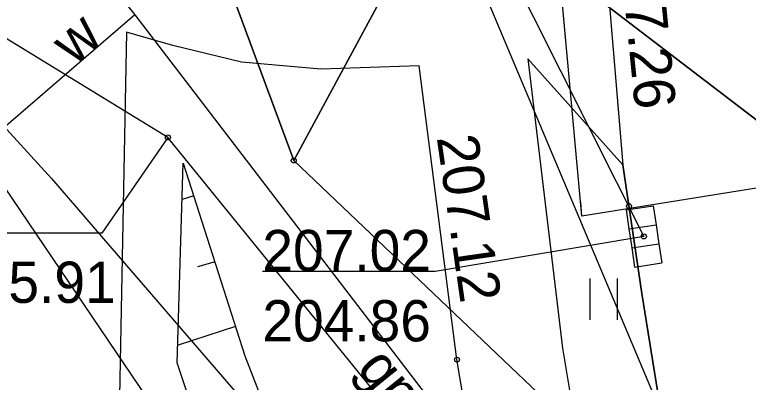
# Model space of a CAD drawing. Extents: x 6512400 to 6513200, y 6022500 to 6022750.
# Drawn here: x 6512830.73 to 6512844.08, y 6022647.71 to 6022654.39 of the extents above; entities that cross this region are included whole.
import ezdxf

# ---------------------------------------------------------------- set-up
doc = ezdxf.new("R2010")
doc.units = 0
for name, color, linetype in [('203-punkt graniczny', 7, 'Continuous'), ('218-kontur użytku gruntowego', 7, 'Continuous'), ('219-działka ewidencyjna', 7, 'Continuous'), ('820-Skarpa nieumocniona', 7, 'Continuous'), ('823-Szczyt skarpy nieumocninej', 7, 'Continuous'), ('824-Podnóże skarpy nieumocninej', 7, 'Continuous'), ('940-Trawnik symb. poj.', 7, 'Continuous'), ('chodnik (powierzchnia)', 7, 'Continuous'), ('inna obudowa przewodu - sieć elektroenergetyczna (linia)', 7, 'Continuous'), ('jezdnia (powierzchnia)', 7, 'Continuous'), ('kratka ściekowa (punkt)', 7, 'Continuous'), ('krawężnik (linia)', 7, 'Continuous'), ('przewód elektroenergetyczny (linia)', 7, 'Continuous'), ('przewód gazowy (linia)', 7, 'Continuous'), ('przewód gazowy (linia)-Atr1', 7, 'Continuous'), ('przewód kanalizacyjny (linia)', 7, 'Continuous'), ('przewód wodociągowy (linia)', 7, 'Continuous'), ('przewód wodociągowy (linia)-Atr1', 7, 'Continuous'), ('punkt o określonej wysokości (sieć gazowa)', 7, 'Continuous'), ('punkt o określonej wysokości (sieć gazowa)-Atr2', 7, 'Continuous'), ('punkt o określonej wysokości (sieć gazowa)-Atr3', 7, 'Continuous'), ('punkt o określonej wysokości (sieć kanalizacyjna)', 7, 'Continuous'), ('punkt o określonej wysokości (sieć kanalizacyjna)-Atr2', 7, 'Continuous'), ('punkt o określonej wysokości (sieć kanalizacyjna)-Atr3', 7, 'Continuous'), ('punkt wysokościowy sztuczny', 7, 'Continuous'), ('punkt wysokościowy sztuczny-Atr2', 7, 'Continuous')]:
    doc.layers.add(name, color=color, linetype=linetype)

# ---------------------------------------------------------------- blocks, each defined once
blk = doc.blocks.new('203')
blk.add_circle((0, 0), 0.045)
blk = doc.blocks.new('PW02')
blk.add_circle((0, 0), 0.045)
blk = doc.blocks.new('940P')
for p, q in [((-0.25, -0.375), (-0.25, 0.375)), ((0.25, -0.375), (0.25, 0.375))]:
    blk.add_line(p, q)
blk = doc.blocks.new('PW01')
blk.add_circle((0, 0), 0.045)
blk = doc.blocks.new('US05')
for p, q in [((-0.525, -0.25), (-0.525, 0.25)), ((-0.525, 0.25), (-0.175, 0.25)), ((-0.175, -0.25), (-0.175, 0.25)), ((-0.175, 0.25), (0.175, 0.25)), ((0.175, -0.25), (0.175, 0.25)), ((0.175, 0.25), (0.525, 0.25)), ((0.525, -0.25), (0.525, 0.25)), ((-0.525, -0.25), (-0.175, -0.25)), ((-0.175, -0.25), (0.175, -0.25)), ((0.175, -0.25), (0.525, -0.25))]:
    blk.add_line(p, q)

msp = doc.modelspace()

# ---------------------------------------------------------------- linework, layer by layer
at = {"layer": '218-kontur użytku gruntowego'}
for points in [[(6512828.67, 6022670.98), (6512835.81, 6022651.74)], [(6512835.81, 6022651.74), (6512828.67, 6022670.98)], [(6512835.81, 6022651.74), (6512838.55, 6022656.82)], [(6512838.55, 6022656.82), (6512835.81, 6022651.74)], [(6512838.55, 6022656.82), (6512856.49, 6022643.11)], [(6512856.49, 6022643.11), (6512838.55, 6022656.82)], [(6512835.81, 6022651.74), (6512852.34, 6022636.01)], [(6512852.34, 6022636.01), (6512835.81, 6022651.74)]]:
    msp.add_lwpolyline(points, dxfattribs=at)
at = {"layer": '219-działka ewidencyjna'}
for points in [[(6512828.67, 6022670.98), (6512835.81, 6022651.74)], [(6512838.55, 6022656.82), (6512835.81, 6022651.74)], [(6512856.49, 6022643.11), (6512838.55, 6022656.82)], [(6512852.34, 6022636.01), (6512835.81, 6022651.74)]]:
    msp.add_lwpolyline(points, dxfattribs=at)
at = {"layer": '820-Skarpa nieumocniona'}
for p, q in [((6512833.99, 6022651.1), (6512833.78, 6022651.03)), ((6512834.38, 6022649.9), (6512834.06, 6022649.81)), ((6512834.75, 6022648.72), (6512833.71, 6022648.38))]:
    msp.add_line(p, q, dxfattribs=at)
at = {"layer": '823-Szczyt skarpy nieumocninej'}
msp.add_lwpolyline([(6512833.8, 6022651.69), (6512834.92, 6022648.19), (6512835.69, 6022646.2), (6512839.8, 6022638.81), (6512840.88, 6022636.68), (6512842.42, 6022630.86), (6512843.78, 6022626.35)], dxfattribs=at)
at = {"layer": '824-Podnóże skarpy nieumocninej'}
msp.add_lwpolyline([(6512843.78, 6022626.35), (6512842.81, 6022626.09), (6512839.81, 6022635.37), (6512839.21, 6022636.76), (6512838.73, 6022638.25), (6512834.42, 6022645.85), (6512833.69, 6022648.06), (6512833.8, 6022651.69)], dxfattribs=at)
at = {"layer": 'chodnik (powierzchnia)'}
for points in [[(6512832.77, 6022654.07), (6512832.63, 6022646.82), (6512837.95, 6022638.9), (6512839.21, 6022636.76), (6512839.81, 6022635.37), (6512842.81, 6022626.09), (6512843.78, 6022626.35), (6512842.42, 6022630.86), (6512840.88, 6022636.68), (6512839.84, 6022641.88), (6512838.78, 6022648.12), (6512838.09, 6022653.46), (6512836.3, 6022653.4), (6512834.86, 6022653.53), (6512833.61, 6022653.83)], [(6512840.07, 6022653.59), (6512840.7, 6022648.33), (6512841.69, 6022642.4), (6512842.69, 6022637.33), (6512844.27, 6022631.32), (6512848.17, 6022618.59), (6512848.25, 6022618.32), (6512848.4, 6022617.84), (6512848.64, 6022617), (6512849.8, 6022613.04), (6512850.26, 6022613.71), (6512850.75, 6022614.71), (6512849.55, 6022618.93), (6512847.18, 6022626.74), (6512845.1, 6022633.98), (6512844.14, 6022637.88), (6512843.35, 6022641.83), (6512842.14, 6022649.32), (6512841.8, 6022651.66)]]:
    msp.add_lwpolyline(points, close=True, dxfattribs=at)
at = {"layer": 'inna obudowa przewodu - sieć elektroenergetyczna (linia)'}
msp.add_lwpolyline([(6512853.31, 6022652.69), (6512841.05, 6022650.73), (6512841.03, 6022650.98)], dxfattribs=at)
at = {"layer": 'jezdnia (powierzchnia)'}
msp.add_lwpolyline([(6512841.12, 6022658.98), (6512841.25, 6022657.96), (6512841.45, 6022655.79), (6512841.8, 6022651.66)], dxfattribs=at)
at = {"layer": 'krawężnik (linia)'}
msp.add_lwpolyline([(6512841.8, 6022651.66), (6512842.14, 6022649.32), (6512843.35, 6022641.83), (6512844.14, 6022637.88), (6512845.1, 6022633.98), (6512847.18, 6022626.74), (6512849.55, 6022618.93), (6512850.75, 6022614.71)], dxfattribs=at)
at = {"layer": 'przewód elektroenergetyczny (linia)'}
msp.add_lwpolyline([(6512856.32, 6022638.43), (6512855.84, 6022638.55), (6512855.94, 6022647.99), (6512853.31, 6022652.69), (6512841.05, 6022650.73), (6512840.36, 6022658.31), (6512832.38, 6022663.33)], dxfattribs=at)
at = {"layer": 'przewód gazowy (linia)'}
msp.add_lwpolyline([(6512847.18, 6022613.76), (6512846.63, 6022615.41), (6512849.08, 6022617.22), (6512845.94, 6022626.61), (6512846.16, 6022628.38), (6512844.18, 6022631.79), (6512844.23, 6022632.26), (6512844.43, 6022634.25), (6512844.47, 6022634.75), (6512844, 6022635.91), (6512842.48, 6022639.61), (6512842.1, 6022640.54), (6512841.83, 6022641.94), (6512833.52, 6022652.16), (6512828.68, 6022655.12), (6512826.33, 6022655.65), (6512824.93, 6022656.06), (6512819.76, 6022660.64)], dxfattribs=at)
at = {"layer": 'przewód kanalizacyjny (linia)'}
for points in [[(6512809.75, 6022675.66), (6512823.01, 6022660.61), (6512831.4, 6022651.41), (6512840.81, 6022640.51)], [(6512853.94, 6022620), (6512836.1, 6022662.34)], [(6512836.14, 6022662.36), (6512842.18, 6022650.36)]]:
    msp.add_lwpolyline(points, dxfattribs=at)
at = {"layer": 'przewód wodociągowy (linia)'}
for points in [[(6512809.35, 6022681.88), (6512813.75, 6022676.76), (6512817.99, 6022672.04), (6512824.14, 6022665.03), (6512827.96, 6022660.57), (6512832.92, 6022654.39), (6512839.85, 6022645.35)], [(6512832.92, 6022654.39), (6512825.7, 6022648.17)], [(6512839.52, 6022638), (6512830.11, 6022651.9), (6512829.45, 6022652.92)]]:
    msp.add_lwpolyline(points, dxfattribs=at)
at = {"layer": 'punkt o określonej wysokości (sieć gazowa)-Atr2'}
msp.add_lwpolyline([(6512833.52, 6022652.16), (6512832.32, 6022650.42), (6512829.503, 6022650.42)], dxfattribs=at)
at = {"layer": 'punkt o określonej wysokości (sieć kanalizacyjna)-Atr2'}
msp.add_lwpolyline([(6512842.18, 6022650.36), (6512838.38, 6022649.72), (6512835.239, 6022649.72)], dxfattribs=at)

# ---------------------------------------------------------------- block references
at = {"layer": '203-punkt graniczny'}
msp.add_blockref('203', (6512835.81, 6022651.74), dxfattribs=at)
at = {"layer": '940-Trawnik symb. poj.'}
msp.add_blockref('940P', (6512841.45, 6022649.22), dxfattribs=at)
at = {"layer": 'kratka ściekowa (punkt)', "rotation": -81.469}
msp.add_blockref('US05', (6512842.18, 6022650.36), dxfattribs=at)
at = {"layer": 'punkt o określonej wysokości (sieć gazowa)'}
msp.add_blockref('PW01', (6512833.52, 6022652.16), dxfattribs=at)
at = {"layer": 'punkt o określonej wysokości (sieć kanalizacyjna)'}
for p, rotation in [((6512841.91, 6022650.91), -62.462), ((6512842.18, 6022650.36), -81.469)]:
    msp.add_blockref('PW01', p, dxfattribs=dict(at, rotation=rotation))
at = {"layer": 'punkt wysokościowy sztuczny'}
msp.add_blockref('PW02', (6512838.78, 6022648.12), dxfattribs=at)

# ---------------------------------------------------------------- texts
at = {"layer": 'przewód gazowy (linia)-Atr1'}
msp.add_text('gn90', height=0.75, rotation=309.115, dxfattribs=at).set_placement((6512836.94, 6022647.95))
at = {"layer": 'przewód wodociągowy (linia)-Atr1'}
msp.add_text('w', height=0.75, rotation=41.585, dxfattribs=at).set_placement((6512831.82, 6022653.45))
at = {"layer": 'punkt o określonej wysokości (sieć gazowa)-Atr3'}
msp.add_text('205.91', height=0.75, dxfattribs=at).set_placement((6512829.503, 6022649.152))
at = {"layer": 'punkt o określonej wysokości (sieć kanalizacyjna)-Atr2'}
msp.add_text('207.02', height=0.75, dxfattribs=at).set_placement((6512835.239, 6022649.728))
at = {"layer": 'punkt o określonej wysokości (sieć kanalizacyjna)-Atr3'}
msp.add_text('204.86', height=0.75, dxfattribs=at).set_placement((6512835.239, 6022648.452))
at = {"layer": 'punkt wysokościowy sztuczny-Atr2'}
for s, rotation, p in [('207.26', 275.669, (6512841.72, 6022655.7)), ('207.12', 278.221, (6512838.41, 6022652.16))]:
    msp.add_text(s, height=0.75, rotation=rotation, dxfattribs=at).set_placement(p)

doc.saveas('drawing.dxf')
